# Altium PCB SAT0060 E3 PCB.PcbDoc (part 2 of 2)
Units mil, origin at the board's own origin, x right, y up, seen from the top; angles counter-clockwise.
Board outline 3780 x 2000 mil, 4 copper layers (Top Layer, L2_GND-Plane, L3_Sig-Layer, Bottom Layer), stack 61.2 mil thick; 136 components, 78 nets, 386 pads, 150 vias.
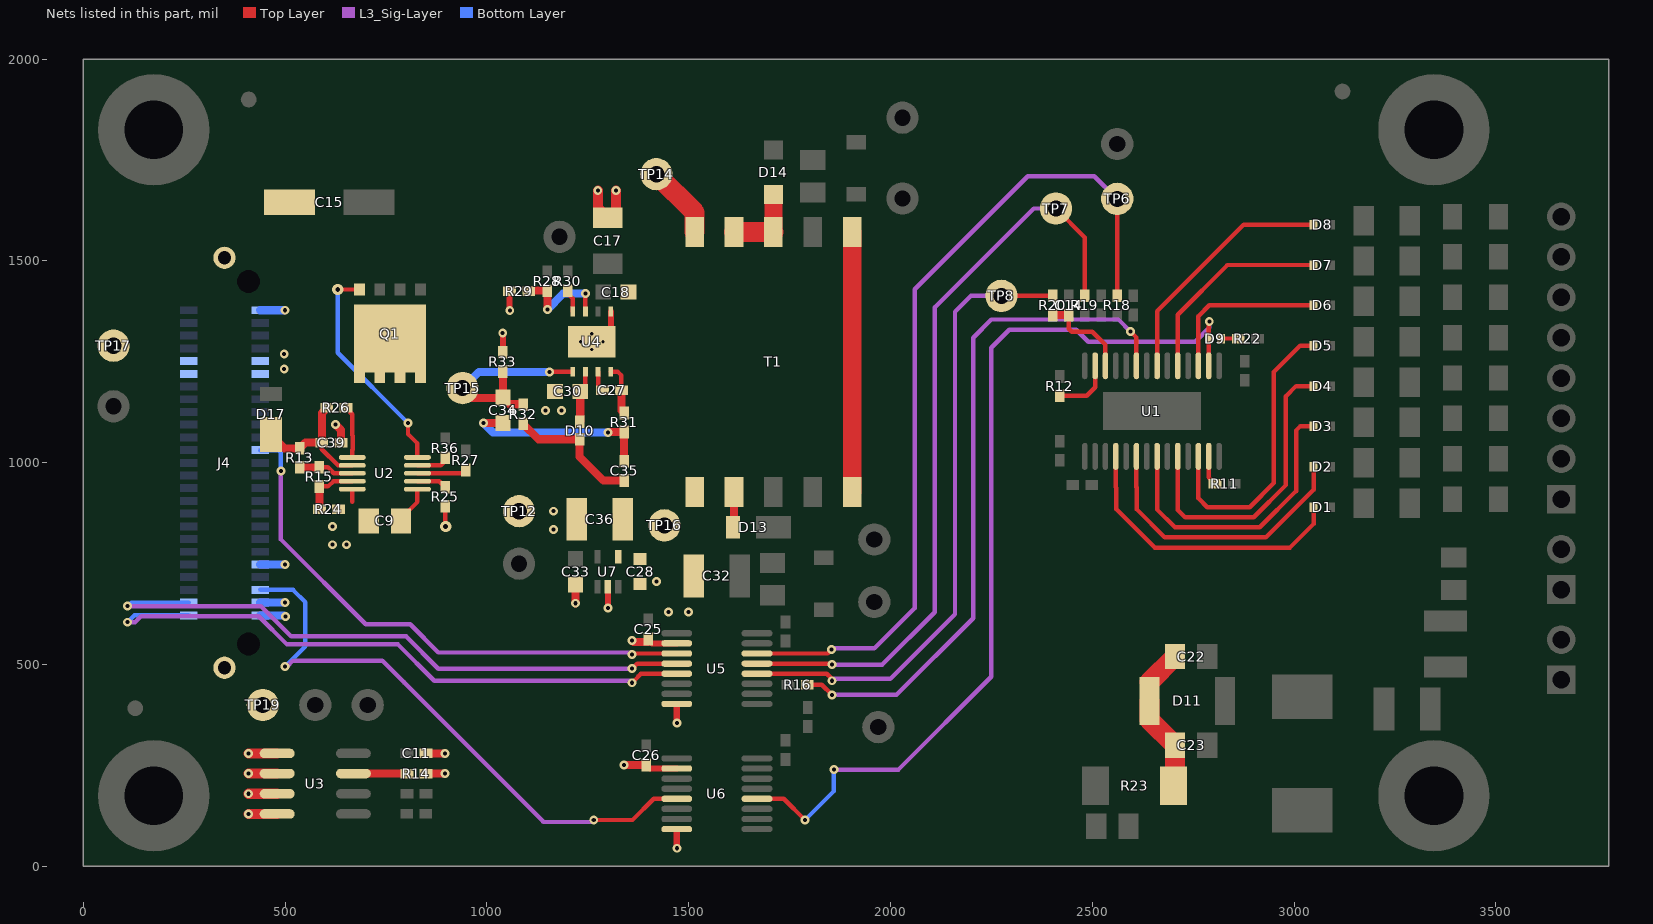
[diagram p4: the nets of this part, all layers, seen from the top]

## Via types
v1: diameter 22, hole 10, Top Layer to Bottom Layer, 126 vias
v2: diameter 15.75, hole 7.87, Top Layer to Bottom Layer, 18 vias
v3: diameter 19.68, hole 7.87, Top Layer to Bottom Layer, 4 vias
v4: diameter 28, hole 12, Top Layer to Bottom Layer, 2 vias

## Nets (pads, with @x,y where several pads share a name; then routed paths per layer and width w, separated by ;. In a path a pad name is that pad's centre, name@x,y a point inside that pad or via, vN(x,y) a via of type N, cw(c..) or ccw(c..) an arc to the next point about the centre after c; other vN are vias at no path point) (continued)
NCS0: J4.1 U5.5 | length 1615
  Top Layer w11: v1(1360,455) 1375.67,470.67 1375.67,471.3 1381.87,477.5 U5.5@1470.59,477.5 1468.79,475.7 U5.5@1477.97,475.7
  L3_Sig-Layer w11: v1(110,605) 128.41,605 143.41,620 435,620 505,550 780,550 870,460 1355,460 v1(1360,455)
  Bottom Layer w11: v1(110,605) 127.05,622.05 J4.1@261.42,622.05
NCS0_ISO: R20.2 TP8.1 U5.12 | length 1564.2
  Top Layer w11: U5.12@1669.41,477.5 1842.5,477.5 v1@1855,465 ; TP8.1@2275,1413.62 R20.2@2401.79,1413.62
  L3_Sig-Layer w11: v1@1860,465 2000,465 2160,625 2160,1374 2199.62,1413.62 TP8.1@2275,1413.62
  other v1: 1855,460
NetC9_1: C9.1 U2.6 | length 73.6
  Top Layer w11: C9.1@798.32,873.32 828.06,903.06 U2.6@828.06,934.64
NetC22_1: C22.1 C23.1 D11.2 R23.2 | length 322.6
  Top Layer w50: D11.2@2641.5,410 2641.5,363.5 C23.1@2705,300 R23.2@2705,203.54 ; D11.2@2641.5,456.5 C22.1@2705,520
NetC27_1: C27.1 U4.7 | length 49.6
  Top Layer w11: U4.7@1275.75,1225.2 1275.75,1190.63 C27.1@1286.38,1180
NetC27_2: C27.2 R31.1 T1.1 TP14.1 U4.8 | length 307.6
  Top Layer w11: U4.8@1307.24,1225.2 1324.8,1225.2 1333.62,1216.38 C27.2@1333.62,1180 ; R31.1@1333.62,1130 R31.1@1340,1123.62
  Top Layer w20: R31.1@1333.62,1130 C27.2@1333.62,1180
  Top Layer w50: TP14.1@1420,1715 1514.72,1620.28 T1.1@1514.72,1572.05
NetC30_1: C30.1 D10.1 U4.6 | length 109.3
  Top Layer w11: C30.1@1244.25,1192.76 U4.6@1244.25,1225.2
  Top Layer w20: D10.1@1231.5,1103.15 C30.1@1231.5,1180
NetC34_1: C34.1 C35.2 R31.2 | length 473.1
  Top Layer w20: v1(991.5,1098.5) C34.1@1040,1098.5 ; v1@1306.38,1076.38 R31.2@1340,1076.38 C35.2@1340,1003.62
  Bottom Layer w20: v1(991.5,1098.5) 1015,1075 v1(1300,1075)
NetC34_2: C34.2 R32.1 R33.2 TP15.1 U4.5 | length 506.4
  Top Layer w11: v1(1155.2,1225.2) U4.5@1212.76,1225.2
  Top Layer w20: TP15.1@940,1185 965,1160 1038.5,1160 C34.2@1040,1161.5 R33.2@1040,1226.38 ; C34.2@1051.5,1150 1056.5,1145 1088.62,1145 R32.1@1090,1143.62
  Bottom Layer w20: TP15.1@940,1185 980.2,1225.2 v1(1155.2,1225.2)
NetC39_1: C39.1 D17.1 R13.2 R26.1 U2.2 | length 345.4
  Top Layer w11: C39.1@591.38,1050 591.38,1033.62 631.3,993.7 U2.2@666.65,993.7
  Top Layer w20: D17.1@465,1069.8 498.96,1035.85 R13.2@537,1035.85 551.15,1050 C39.1@591.38,1050 591.38,1123.47 R26.1@603.73,1135.82
NetD9_1: D9.1 R22.1 | length 42.7
  Top Layer w11: D9.1@2819.43,1307.87 R22.1@2862.09,1307.87
NetD13_2: D13.2 T1.9 | length 89
  Top Layer w20: D13.2@1609.8,840 1612.36,842.56 T1.9@1612.36,927.95
NetD14_2: D14.2 T1.2 T1.3 | length 190.5
  Top Layer w45: T1.3@1710,1572.05 D14.2@1710,1664.88
  Top Layer w50: T1.2@1612.36,1572.05 T1.3@1710,1572.05
NetQ1_4: Q1.4 U2.10 | length 551.5
  Top Layer w11: v4(630.7,1429.3) Q1.4@684.51,1429.3 ; v1(804.76,1098.42) 804.76,1071.24 828.06,1047.94 U2.10@828.06,1013.38
  Bottom Layer w11: v4(630.7,1429.3) 630.7,1272.48 v1(804.76,1098.42)
NetQ1_5: Q1.5 Q1.6 Q1.7 Q1.8 Q1.9 R26.2 U2.1 | length 129.8
  Top Layer w11: R26.2@650.98,1135.82 666.65,1120.15 666.65,1068.34 667.67,1067.32 667.67,1032.68 666.65,1031.66 U2.1@666.65,1013.38
NetR11_2: R11.2 U1.13 | length 74.3
  Top Layer w11: U1.13@2788.68,1015.98 2788.68,963.82 R11.2@2804.31,948.19
NetR12_2: R12.2 U1.27 | length 149
  Top Layer w11: R12.2@2420,1166.38 2486.38,1166.38 2507.18,1187.18 U1.27@2507.18,1240.39
NetR13_1: R13.1 R15.2 U2.3 | length 135.7
  Top Layer w11: R15.2@580,988.62 R15.2@585,988.62 606.38,988.62 620.99,974.01 U2.3@666.65,974.01
  Top Layer w20: R13.1@537,988.6 R15.2@580,988.62
NetR14_1: R14.1 U3.7 | length 128.1
  Top Layer w11: U3.7@669.06,230 U3.7@669.49,230
  Top Layer w20: U3.7@669.49,230 R14.1@797.17,230
NetR15_1: R15.1 R24.2 U2.4 | length 143.5
  Top Layer w11: R15.1@585,941.38 606.38,941.38 619.33,954.33 U2.4@666.65,954.33
  Top Layer w20: R15.1@585,941.38 585,885.38 R24.2@585.38,885
NetR25_2: R25.2 U2.7 | length 75.5
  Top Layer w11: U2.7@828.06,954.33 882.47,954.33 R25.2@897.35,939.45
NetR27_2: R27.2 U2.8 | length 122.7
  Top Layer w11: U2.8@828.06,974.01 939.17,974.01 R27.2@947.35,982.2
NetR28_1: R28.1 R29.2 U4.3 | length 241.3
  Top Layer w11: U4.3@1244.25,1374.8 v1(1244.25,1419.25)
  Top Layer w20: R29.2@1110,1426.38 R28.1@1150,1426.38 v1(1150,1380)
  Bottom Layer w20: v1(1150,1380) 1189.25,1419.25 v1(1244.25,1419.25)
NetR30_1: R30.1 U4.4 | length 56.9
  Top Layer w11: R30.1@1200,1426.38 1200,1420 1212.76,1407.24 U4.4@1212.76,1374.8
NetR36_2: R36.2 U2.9 | length 80.9
  Top Layer w11: U2.9@828.06,993.7 885.7,993.7 897.2,1005.2 R36.2@897.2,1012.2
NetT1_5: T1.5 T1.6 | length 644.1
  Top Layer w45: T1.6@1905.28,927.95 T1.5@1905.28,1572.05
NHOT_ISO: D9.2 U1.16 U6.12 | length 2298.9
  Top Layer w11: U6.12@1669.41,167.5 1735.91,167.5 v1(1788.41,115) ; U1.16@2788.68,1240.39 D9.2@2788.68,1307.87 v1@2788.68,1343.68
  L3_Sig-Layer w11: v1(1860,240) 2020,240 2250,470 2250,1285 2294.3,1329.3 2460.7,1329.3 2490,1300 2755,1300 2790,1335 v1(2790,1350)
  Bottom Layer w11: v1(1788.41,115) 1860,186.59 v1(1860,240)
NLD: C14.1 R20.1 U1.26 | length 233.5
  Top Layer w11: C14.1@2441.79,1366.38 2441.79,1332.21 2449,1325 2500,1325 2532.77,1292.23 U1.26@2532.77,1240.39
  Top Layer w20: R20.1@2401.79,1366.38 C14.1@2441.79,1366.38
NSDRDY: J4.6 U6.5 | length 1466.5
  Top Layer w11: v1(1265,115) 1361,115 1413.5,167.5 U6.5@1470.59,167.5
  L3_Sig-Layer w11: v1@505,495 520,510 741,510 795.2,455.8 ; 795.2,454.8 795.2,455.8 ; 1140,110 1260,110 v1(1265,115) ; 1140,111 795.2,455.8
  Bottom Layer w11: J4.6@438.58,685.04 519.96,685.04 550,655 550,545 v1(500,495)
PLC_GND: C9.2 C11.2 C15.2 C17.2 C18.2 C25.2 C26.2 C28.1 C30.2 C32.2 C33.2 C36.2 C39.2 J4.2 J4.4 J4.10 J4.39 J4.40 J4.41 J4.42 J4.50 J4.MH1 J4.MH2 R14.2 R24.1 R25.1 R29.1 R33.1 TP12.1 TP17.1 TP19.1 U2.5 U3.1 U3.2 U3.3 U3.4 U4.1 U4.9 U5.2 U5.8 U6.2 U6.8 U7.2 | length 1552.2
  Top Layer w11: 666.65,903.65 U2.5@666.65,934.64 ; R25.1@897.35,892.2 897.35,842.65 v4(898,842)
  Top Layer w15: R33.1@1040,1273.62 v1@1040,1320.53 ; v1@1056.38,1378.09 R29.1@1056.38,1425 ; U4.9@1260,1300 1283,1300 1307.24,1324.24 U4.1@1307.24,1374.8 ; v1(1300,640) U7.2@1300,692.91 ; C26.2@1395,251.38 1403.88,242.5 U6.2@1470.59,242.5 ; C25.2@1400,561.38 1408.88,552.5 U5.2@1470.59,552.5 ; v1@1470.59,45.59 U6.8@1470.59,92.5 ; v1@1470.59,355.59 U5.8@1470.59,402.5
  Top Layer w20: v1(625,1095) 638.62,1081.38 C39.2@638.62,1050 ; R14.2@849.41,230 v1(896.22,230) ; C11.2@849.41,280 v1(896.22,280) ; v1(1220,652.01) C33.2@1220,698.82 ; C36.2@1222.91,852.09 C36.2@1222.91,860 ; v1(1340,251.38) C26.2@1395,251.38 ; v1(1360,560) 1363.62,556.38 C25.2@1400,556.38
  Top Layer w25: v1(410,130) U3.4@480.51,130 ; v1(410,180) U3.3@480.51,180 ; v1(410,230) U3.2@480.51,230 ; v1(410,280) U3.1@480.51,280 ; v1(1275,1675) 1275,1632.09 C17.2@1300,1607.09 1320,1627.09 v1(1320,1675)
  Bottom Layer w20: J4.2@438.58,622.05 v1@492.95,622.05 ; J4.4@438.58,653.54 v1@497.95,653.54 ; J4.10@438.58,748.03 v1@497.95,748.03 ; J4.50@438.58,1377.95 v1@497.95,1377.95 ; v1@497.95,622.05 v1(501,619)
  other v1: 1471.18,45 1471.18,355 1450,630 1500,630 500,653.54 1420,706 500,748.03 618,797 652,797 1165,835 618,842 1165,880 1145,1130 1185,1130 498,1232 498,1270 1039.41,1321.12 500,1377.95 1056.97,1377.5
  other v3: 1260,1280.32 1232.44,1300 1287.56,1300 1260,1319.68
RE0: D1.1 U1.4 | length 727.5
  Top Layer w11: U1.4@2558.37,1015.98 2558.37,940 2560,938.37 2560,885 2655,790 2990,790 3048.35,848.35 D1.1@3048.35,888.35 ; D1.1@3048.35,890 D1.1@3048.35,888.35 ; D1.1@3050,890 D1.1@3048.35,888.35
RE1: D2.1 U1.6 | length 704.2
  Top Layer w11: U1.6@2609.55,1015.98 2609.55,940 2610.7,938.85 2610.7,884.3 2680,815 2930,815 3048.35,933.35 D2.1@3048.35,990
RE2: D3.1 U1.8 | length 729.1
  Top Layer w11: U1.8@2660.73,1015.98 2660.73,884.27 2705,840 2915,840 3005,930 3005,1080 3015,1090 D3.1@3048.35,1090
RE3: D4.1 U1.10 | length 740.3
  Top Layer w11: U1.10@2711.91,1015.98 2711.91,883.09 2730,865 2900,865 2980,945 2980,1165 3005,1190 D4.1@3048.35,1190
RE4: D5.1 U1.12 | length 725.2
  Top Layer w11: U1.12@2763.09,1015.98 2763.09,911.91 2785,890 2890,890 2950,950 2950,1225 3015,1290 D5.1@3048.35,1290
RE5: D6.1 U1.17 | length 419.1
  Top Layer w11: U1.17@2763.09,1240.39 2763.09,1363.09 2790,1390 D6.1@3048.35,1390
RE6: D7.1 U1.19 | length 513.9
  Top Layer w11: U1.19@2711.91,1240.39 2711.91,1366.91 2835,1490 D7.1@3048.35,1490
RE7: D8.1 U1.21 | length 613.5
  Top Layer w11: U1.21@2660.73,1240.39 2660.73,1375.73 2875,1590 D8.1@3050.13,1590
S1GPO0: J4.28 U5.3 | length 1368.8
  Top Layer w11: v1(1360,525) 1362.5,527.5 U5.3@1470.59,527.5
  L3_Sig-Layer w11: v1(490,980) 490,810 700,600 810,600 880,530 1355,530 v1(1360,525)
  Bottom Layer w11: J4.28@438.58,1031.5 483.5,1031.5 490,1025 v1(490,980)
S1GPO0_ISO: R18.2 TP6.1 U5.14 | length 2127.2
  Top Layer w11: U5.14@1669.41,527.5 1844.5,527.5 v1(1854,537) ; R18.2@2561.79,1413.62 TP6.1@2561.79,1654.12
  L3_Sig-Layer w11: v1@1857,540 1960,540 2060,640 2060,1430 2340,1710 2505,1710 2560,1655 TP6.1@2560,1630
SCLK: J4.3 U5.4 | length 1572.8
  Top Layer w11: v1(1360,490) 1372.5,502.5 U5.4@1470.59,502.5
  L3_Sig-Layer w11: v1(110,645) 440,645 515,570 800,570 880,490 v1(1360,490)
  Bottom Layer w11: 118.54,653.54 J4.3@261.42,653.54
SCLK_ISO: R19.2 TP7.1 U5.13 | length 1894.5
  Top Layer w11: U5.13@1669.41,502.5 v1@1852.5,502.5 ; TP7.1@2410,1630 2481.79,1558.21 R19.2@2481.79,1413.62
  L3_Sig-Layer w11: v1(1855,500) 1980,500 2110,630 2110,1385 2355,1630 TP7.1@2410,1630
SOP: R16.1 U1.23 | length 1707.1
  Top Layer w11: R16.1@1793.62,450 1830,450 v1(1855,425) ; v1(2595,1325) 2609.55,1310.45 U1.23@2609.55,1240.39
  L3_Sig-Layer w11: v1(1855,425) 2015,425 2205,615 2205,1310 2250,1355 2565,1355 v1(2595,1325)
VPRI: C28.2 C35.1 C36.1 D10.2 R32.2 T1.10 TP16.1 U7.4 | length 333.4
  Top Layer w20: R32.2@1090,1096.38 1128.03,1058.35 D10.2@1230,1058.35 1230,1015 1288.62,956.38 C35.1@1340,956.38
pads on no net: FID1.1 FID2.1 FID3.1 H1.1 H2.1 H5.1 H6.1 J4.7 J4.8 J4.9 J4.13 J4.14 J4.15 J4.16 J4.17 J4.18 J4.19 J4.20 J4.21 J4.22 J4.23 J4.24 J4.25 J4.26 J4.30 J4.31 J4.32 J4.33 J4.34 J4.43 J4.44 J4.45 J4.46 J4.47 J4.48 J4.49 J4.MH3 J4.MH4 LBL1.0 T1.7 T1.8 U1.14 U6.6 U6.11 U7.1 U7.3

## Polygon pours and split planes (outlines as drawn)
PLC_GND on Bottom Layer "Bottom Layer-No Net" (solid, remove dead copper, shelved, pour order 7): 15.9,1980 1540,1980 1540,20 6.32,20 6.32,1960.4 15.9,1970.2
ISO_GND on Bottom Layer "Top Layer-No Net" (solid, shelved, pour order 8): 1604.77,1975.07 1599.85,1970.05 1599.85,20 3760.98,20 3765.81,24.93 3765.81,1980 1604.67,1980 1590,1965.02 1594.92,1970.05 1599.85,1970.05 1599.85,1975.07
PLC_GND on Top Layer "Top Layer-No Net 1" (solid, shelved, pour order 6): 6.32,2000.53 6.32,29.89 0.19,15 2.23,19.96 1540,19.96 1540,1980.53 1535.05,1980.53 1529.79,1980.68 8.44,1980.68
ISO_GND on Top Layer "Top Layer-No Net" (solid, remove dead copper, shelved, pour order 5): 1604.94,1971.13 1600.02,1966.11 1600.02,16.06 3761.16,16.06 3765.98,20.99 3765.98,1976.06 1604.85,1976.06 1590.17,1961.08 1595.1,1966.11 1600.02,1966.11 1600.02,1971.13
ISO_GND on Top Layer "Top Layer-No Net" (hatched 90Degree grid 5 track 8, remove dead copper, pour order 36): 1660,98.01 1660,49.43 1670,39.72 1680,30 1735,30 3205,30 3225,49.43 3225,185.46 3225,300.11 3208,316.63 3198,326.35 3170,326.35 3143,300.11 3070,229.18 2948,229.18 2825,229.18 2800,204.89 2740,146.6 2623,146.6 2579,146.6 2560,128.13 2560,78.58 2550,68.87 2460,68.87 2430,68.87 2420,78.58 2420,151.45 2420,370.07 2310,476.95 2065,715 1910,715 1885,690.71 1725,690.71 1675,690.71 1660,676.13 1660,627.55 1660,98.01
PLC_GND on Top Layer "Top Layer-No Net" (hatched 90Degree grid 5 track 8, remove dead copper, pour order 26): 1400,1460 1410,1450 1410,1345 1325,1260 1125,1260 1115,1270 1115,1310 1140,1335 1339.65,1335 1354,1349.35 1354,1450.27 1363.73,1460
ISO_GND on Top Layer "Top Layer-No Net" (hatched 90Degree grid 5 track 8, remove dead copper, pour order 35): 3350,825 3695,825 3715,806.41 3715,778.53 3700,764.59 3690,755.29 3610,755.29 3455,755.29 3450,750.65 3445,746 3365,746 3340,746 3325,759.94 3320,764.59 3320,801.76 3320,811.06 3335,825 3350,825
PLC_GND on Top Layer "Top Layer-No Net" (hatched 90Degree grid 5 track 8, remove dead copper, pour order 34): 1450,715 1475,740 1515,740 1525,730 1525,625 1510,610 1450,610 1435,625 1435,650 1415,670 1365,670 1355,680 1355,710 1360,715
PLC_GND on Top Layer "Top Layer-No Net" (hatched 90Degree grid 5 track 8, remove dead copper, pour order 33): 1245,805 1155,805 1135,825 1130,830 1075,830 1030,830 1020,840 1015,845 1015,905 1015,935 1030,950 1090,950 1225,950 1235,940 1245,930 1245,910 1245,805
ISO_GND on Top Layer "Top Layer-No Net" (hatched 90Degree grid 5 track 8, remove dead copper, pour order 32): 3240,439 3240,300 3175,235 3175,70 3160,55 2815,55 2800,70 2800,190 2825,215 3070,215 3175,320 3175,435 3179,439
24V_LIMIT on Top Layer "Top Layer-No Net" (hatched 90Degree grid 5 track 8, remove dead copper, pour order 30): 945,1020 915,1050 860,1050 850,1060 850,1090 860,1100 920,1100 965,1055 1015,1055 1025,1045 1025,1030 1015,1020
PLC_GND on Top Layer "Top Layer-No Net" (hatched 90Degree grid 5 track 8, remove dead copper, pour order 29): 715,780 725,790 725,875 720,880 690,880 685,885 685,905 680,910 625,910 620,905 620,865 600,845 600,790 610,780
24V_LIMIT on Top Layer "Top Layer-No Net" (hatched 90Degree grid 5 track 8, remove dead copper, pour order 28): 1305,1410 1285,1410 1270,1420 1270,1455 1260,1465 965,1465 925,1425 828,1425 724,1426 710,1440 710,1510 640,1580 640,1840 665,1865 900,1865 950,1815 1090,1815 1235,1670 1235,1555 1250,1540 1300,1540 1310,1530 1310,1415
PLC_GND on Top Layer "Top Layer-No Net" (hatched 90Degree grid 5 track 8, remove dead copper, pour order 25): 1185,1115 1140,1115 1130,1125 1130,1185 1140.02,1195 1178.35,1195 1190,1190 1190,1120
PLC_GND on Top Layer "Top Layer-No Net" (hatched 90Degree grid 5 track 8, remove dead copper, pour order 24): 425,1360 535,1360 555,1360 580,1385 580,1455 580,1775 560,1795 555,1800 460,1800 410,1800 400,1790 300,1690 300,1550 300,1390 330,1360 425,1360
NetQ1_5 on Top Layer "Top Layer-No Net" (hatched 90Degree grid 5 track 8, remove dead copper, pour order 23): 684,1110 655.15,1110 641.13,1124.01 641.13,1178.87 640,1180 640,1385 649.96,1395 860,1395 870,1385 870,1310 870.04,1285 870.04,1145.04 850,1125 699,1125
ISO_GND on Top Layer "Top Layer-No Net" (hatched 90Degree grid 5 track 8, remove dead copper, pour order 27): 2675,130 2680,125 2680,70 2670,60 2575,60 2560,75 2560,130 2565,135 2585,135 2590,130
PLC_GND on Top Layer "Top Layer-No Net" (hatched 90Degree grid 5 track 8, remove dead copper, pour order 40): 1485,40 1485,585 1521,621 1521,727 1508,740 1295,740 1265,770 1265,940 1415,1090 1415,1585 1445,1615 1500,1615 1525,1640 1525,1965 1515,1975 155,1975 40,1860 40,130 135,35 1480,35
ISO_GND on Top Layer "Top Layer-No Net" (hatched 90Degree grid 5 track 8, remove dead copper, pour order 38): 2000,880 2030,850 2090,850 2550,390 2550,265 2560,255 2640,255 2650,265 2650,300 2605,345 2605,525 2670,590 2730,590 2890,750 3730,750 3750,770 3750,1955 3730,1975 1635,1975 1615,1955 1615,1645 1630,1635 1950,1635 2000,1585
24V_LIMIT on Bottom Layer "Top Layer-No Net" (hatched 90Degree grid 5 track 8, remove dead copper, pour order 31): 1015,1010 850,1010 835,1025 835,1100 835,1108 783,1160 748,1195 748,1775 778,1805 923,1805 933,1795 968,1760 968,1735 968,1484 935,1451 885,1401 885,1280 885,1140 905,1120 974,1051 980,1051 1015,1051 1025,1041 1025,1020 1025,1015 1020,1010 1015,1010
PLC_GND on Bottom Layer "Top Layer-No Net" (hatched 90Degree grid 5 track 8, remove dead copper, pour order 39): 1485,40 1485,585 1521,621 1521,727 1508,740 1295,740 1265,770 1265,940 1415,1090 1415,1585 1445,1615 1505,1615 1520,1630 1520,1950 1495,1975 155,1975 40,1860 40,130 135,35 1480,35
ISO_GND on Bottom Layer "Top Layer-No Net" (hatched 90Degree grid 5 track 8, remove dead copper, pour order 37): 2000,915 1885,850 1885,700 1661.2,700 1660,381 1660,51 1683,30 2508,50 3700,50 3750,100 3750,1955 3730,1975 1640,1975 1615,1950 1615,1650 1630,1635 1950,1635 2000,1585
ISO_GND on L2_GND-Plane (split plane): 3759.9,20.1 1605.09,20.1 1605.09,1979.9 3759.9,1979.9
PLC_GND on L2_GND-Plane (split plane): 1534.9,20.1 20.1,20.1 20.1,1979.9 1534.9,1979.9

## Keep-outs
Keep-Out Layer:
  text ".Layer_Name" at 577,-858.49 h60

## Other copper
Top Layer:
  rectangle net PLC_GND: 1497,545 1524,560
  pour cut-out: 615,1040 650,1040 655,1035 655,1015 650,1010 625,1010 610,1025 610,1035
  pour cut-out: 705,935 710,930 710,920 700,910 615,910 615,930 620,935
  pour cut-out: 613.58,900 645,931.42 645,960 640,965 610,965 606.38,961.38 606.38,923.38 600,917 600,900
  pour cut-out: 3249,443.15 3135.29,443.15 3135.29,475.29 3230,570 3270,570 3270,309 3249,289
  region net 24V_FIELD: 3712.43,723 3712.43,643.25 3557.44,643.25 3494.19,580 3221,580 3120,479 3120,350 2913.59,350 2823.59,260 2754,260 2754,331.44 2790.12,367.56 2790.12,452.88 2757,486 2757,567 2895,705 3502.21,705 3520.21,723
  region net EARTH_GND: 3710.01,610 3710.01,380.01 3666.85,336.85 3309,336.85 3309,530 3540,530 3627.99,610
  region net 5V_ISO: 2469.77,957.46 2469.77,870 2382.23,870 2294.77,957.46 2294.77,1297 2368,1297 2438,1227 2438,1194 2374,1194 2344.77,1164.77 2344.77,1073 2436,1073 2436,1036 2344.77,1036 2344.77,985.23 2372.54,957.46
  pour cut-out: 3431.54,1656.5 3468.46,1656.5 3468.46,863.5 3431.54,863.5
  pour cut-out: 920.67,906.7 920.5,906.53 920.5,768 596.5,768 596.5,861.35 581.5,861.35 581.5,759 587.5,753 936.5,753 936.5,902 928.5,910 925.2,906.7
  pour cut-out: -15,1865 -15,1985 105,1985 115,1975 5,1865
  pour cut-out: 110,10 -10,10 -10,130 0,140 110,30
  region net 24V_PLC: 435.82,1199 435.82,1145 565,1145 579.85,1159.85 579.85,1231 535,1231 535,1199
  region net NetC27_2: 1539.97,1600 1510.12,1600.12 1490,1580 1490,1410 1320,1240 1300,1240 1300,1213 1318,1195 1318,1106 1357,1106 1357,1202 1540,1385 1540,1570
  region net VPRI: 1540,860 1425,745 1310,745 1310,956.81 1323.19,970 1540,970
  region net ISO_GND: 3100.5,75 2829.5,75 2805.5,99 2805.5,179 2830.5,204 3100.5,204
  pour cut-out: 2893,1371 2892.84,1370.84 2892.84,1333.7 2810.79,1333.7 2809,1331.91 2809,1376 2893,1376
  region net NetC39_1: 620,1124 603,1107 603,1020 431,1020 431,1118.4 442.3,1129.71 569.71,1129.71 592,1152 620,1152
  pour cut-out: 746.35,901.32 700.32,901.32 699,900 699,1034 683,1034 684,1110 763.81,1107.89 762.66,1072.42 783.32,1071.38 806.22,1032.62 786,1008 780.94,943.49 805,900
  text ".Layer_Name" at 577,-858.49 h60
L3_Sig-Layer:
  text ".Layer_Name" at 565,-860 h60
Bottom Layer:
  rectangle net PLC_GND: 597,824 643,1115
  region net 5V_ISO: 2108,1478.22 2165,1478.22 2165,544 2108,544
  pour cut-out: 581.21,1131.29 581.21,1116 657.65,1116 657.65,1131.29
  pour cut-out: 581.35,824 596.65,824 596.65,1115 581.35,1115
  pour cut-out: 642.35,824 657.65,824 657.65,1115.32 642.35,1115.32
  pour cut-out: 581.21,823.29 581.21,808 657.65,808 657.65,823.29
  region net PLC_GND: 20,1211.1 20,1350 135,1350 178.48,1263.03 478,1265 478,1293 520,1293 520,1211.1
  region net 24V_PLC: 20,1199 20,1090 140,1090 168.52,1147.04 580,1145 580,1232 535,1232 535,1199
  text ".Layer_Name" at 577,-858.49 h60
L2_GND-Plane (plane layer: these items are gaps in the copper):
  rectangle: 595.35,822 641,862.32
  rectangle: 602.35,1075 648,1115.32
  lines w10: 1540,-10 1540,2010
  lines w60: 1575,20 1575,1980
  text ".Layer_Name" at 575,-860 h60

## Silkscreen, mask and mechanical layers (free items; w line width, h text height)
Top Overlay:
  lines w8: 957,1243 1003,1289 1003,1319 ; 1878,735 2075,735 ; 2116.16,682.45 2084,682.45 2074,692.45 2074,779.55 2074,785.29 2081.16,792.45 2116.16,792.45 ; 3139,1821 3139,1683 ; 3173,697 3173,835 ; 3139,1683 3129,1693 3149,1693 3139,1683 ; 3173,835 3163,825 3183,825 3173,835
  text "GND" at 3510,735 h40 r90
  text "SAT0060 E2" at 301.57,660.82 h40 r90
  text "ISE-PLC-DIM-100" at 373,660 h40 r90
  text "24V" at 3515,645 h40 r90
  text "EARTH_GND" at 3510,380 h40 r90
  text ".Layer_Name" at 577,-858.49 h50
Bottom Overlay:
  text "50" at 561,1402 h45
  text "49" at 217,1370 h45
  text "1" at 212,591 h45
  text "2" at 518,553 h45
  text ".Layer_Name" at 577,-858.49 h60
Top Paste:
  text ".Layer_Name" at 577,-858.49 h60
Bottom Paste:
  text ".Layer_Name" at 577,-858.49 h60
Top Solder:
  text ".Layer_Name" at 577,-858.49 h60
  text ".Layer_Name" at 577,-858.49 h60
Bottom Solder:
  text ".Layer_Name" at 577,-858.49 h60
Drill Guide:
  text ".Layer_Name" at 577,-858.49 h60
M1 Board Outline:
  the board outline again, w10
  text ".Layer_Name" at 577,-858.49 h60
M2 Board Dimensions:
  rectangle: -0.5,-285.5 124.5,-160.5
  rectangle: 124.5,-410.5 499.5,-285.5
  lines w7: -0.5,-285.5 999.5,-285.5 ; 124.5,-410.5 124.5,-160.5 ; 249.5,-410.5 249.5,-160.5 ; 499.5,-410.5 499.5,-160.5 ; 749.5,-410.5 749.5,-160.5 ; -0.5,-410.5 999.5,-410.5 999.5,-160.5 -0.5,-160.5 -0.5,-410.5
  lines w10: -0.5,-475.5 -0.5,-455.5 ; 59.5,-485.5 -0.5,-465.5 ; 59.5,-445.5 -0.5,-465.5 ; 223.58,-465.5 -0.5,-465.5 ; 775.42,-465.5 999.5,-465.5 ; 939.5,-485.5 999.5,-465.5 ; 939.5,-445.5 999.5,-465.5 ; 999.5,-475.5 999.5,-455.5
  text "1000 (mil)" at 233.58,-501.49 h60
  text ".Layer_Name" at 577,-858.49 h60
M3 3D STEP Top:
  text ".Layer_Name" at 577,-858.49 h60
M4 3D STEP Bottom:
  text ".Layer_Name" at 577,-858.49 h60
M5 Assembly Top:
  lines w10: -292,-930.17 6308,-930.17 ; -292,-726.83 6310,-726.83 ; -292,-523.5 -292,-1133.5 3713,-1133.5 6310,-1133.5 6310,-523.5 -291.5,-523.5 -291.5,-1133.5 1284,-1133.5 ; 2173,-1133.5 2173,-523.5 ; 3440,-726.83 3440,-523.5 ; 4280,-726.83 4280,-523.5 ; 4902,-1140 4902,-937.17
  text "COMPONENTS MARKED 'DNP' SHOULD NOT BE POPULATED." at 1153.5,-318.5 h60
  text "ASSEMBLY VARIANT:" at 1153,-434 h60
  text ".VariantName" at 2189,-434 h60
  text "PCB VIEWED FROM TOP SIDE" at -228.5,-655.67 h60
  text "BOARD #:" at 2248,-655.67 h60
  text ".PRJ_Number" at 2793.5,-655.67 h60
  text "REV:" at 3638,-655.67 h60
  text ".PCB_Rev" at 3929.5,-655.67 h60
  text "SVN REV:" at 4476,-655.67 h60
  text ".VersionControl_RevNumber" at 4982,-655.67 h60
  text "IGNORE ->" at -228.5,-858.49 h60
  text "PLOT NAME =" at -228.5,-1064.34 h60
  text ".plot_File_Name" at 577,-1064.34 h60
  text "GENERATED    :" at 2250,-1064.34 h60
  text ".Print_Date" at 3119.5,-1064.34 h60
  text ".Print_Time" at 3848.5,-1064.34 h60
  text "TEXAS INSTRUMENTS" at 5113,-1064.34 h60
M6 Assembly Bottom:
  lines w10: -292.5,-727.33 6309.5,-727.33 ; -290.5,-930.67 6309.5,-930.67 ; 1115.5,-1140.5 1115.5,-937.67 ; 1737.5,-727.33 1737.5,-524 ; 2577.5,-727.33 2577.5,-524 ; 3844.5,-1134 3844.5,-524 ; 4733.5,-1134 6309,-1134 6309,-524 -292.5,-524 -292.5,-1134 2304.5,-1134 6309.5,-1134 6309.5,-524
  text "COMPONENTS MARKED 'DNP' SHOULD NOT BE POPULATED." at 6102,-318 h60
  text ".VariantName" at 5058,-434 h60
  text "ASSEMBLY VARIANT:" at 6097,-434 h60
  text ".VersionControl_RevNumber" at 1035.5,-656.17 h60
  text "SVN REV:" at 1541.5,-656.17 h60
  text ".PCB_Rev" at 2088,-656.17 h60
  text "REV:" at 2379.5,-656.17 h60
  text ".PRJ_Number" at 3224,-656.17 h60
  text "BOARD #:" at 3769.5,-656.17 h60
  text "PCB VIEWED FROM BOTTOM SIDE" at 6246,-656.17 h60
  text "IGNORE ->" at 2547.85,-858.49 h60
  text "TEXAS INSTRUMENTS" at 904.5,-1064.84 h60
  text ".Print_Time" at 2169,-1064.84 h60
  text ".Print_Date" at 2898,-1064.84 h60
  text "GENERATED    :" at 3767.5,-1064.84 h60
  text ".plot_File_Name" at 5440.5,-1064.84 h60
  text "PLOT NAME =" at 6246,-1064.84 h60
M9 Title Sheet:
  drawing of 57 lines, arcs and shapes, not listed
  text "1" at 739.84,8036.5 h70
  text "2" at 3235.5,8036.5 h70
  text "3" at 5724.84,8036.5 h70
  text "4" at 8231.51,8036.5 h70
  text "5" at 10730.5,8036.5 h70
  text "6" at 13235.5,8036.5 h70
  text "A" at -416.5,6893.5 h70
  text "A" at 14383.5,6893.5 h70
  text "B" at -416.5,4513.5 h70
  text "B" at 14383.5,4513.5 h70
  text "C" at -416.5,2138.5 h70
  text "C" at 14383.5,2138.5 h70
  text "PROJECT TITLE:" at 11343.5,277.5 h45
  text ".PRJ_Title" at 11393.5,144.17 h70
  text "DESIGNED FOR:" at 11343.5,-23.5 h45
  text ".PRJ_Customer" at 11393.5,-163.5 h70
  text "D" at -416.5,-231.5 h70
  text "D" at 14383.5,-231.5 h70
  text "FILE NAME:" at 11343.5,-323.5 h45
  text ".PCB_File_Name_No_Path" at 11393.5,-443.5 h70
  text "Texas Instruments (TI) and/or its licensors do not warrant the accuracy or completeness of this specification" at 6374,-605.34 h45
  text "ENGINEER:" at 11343.5,-613.5 h45
  text "LAYOUT BY:" at 12848.5,-613.5 h45
  text "or any information contained therein. TI and/or its licensors do not warrant that this design will meet" at 6329.01,-718 h45
  text ".PRJ_Engineer" at 11393.5,-768.49 h70
  text ".PCB_Layout" at 12899,-768.49 h70
  text "the specifications, will be suitable for your application or fit for any particular purpose, or will operate in" at 6329.01,-830.67 h45
  text ".Layer_Name" at 577,-858.49 h60
  text "ALTIUM DESIGNER VERSION:" at 12848.5,-923.5 h45
  text "an implementation. TI and/or its licensors do not warrant that the design is production worthy. You should" at 6329.01,-943.33 h45
  text "completely validate and test your design implementation to confirm the system functionality for your application." at 6374,-1056 h45
  text ".print_Scale" at 11393.5,-1056.83 h70
  text ".Application_BuildNumber" at 12899,-1056.83 h70
  text "1" at 739.84,-1263.5 h70
  text "2" at 3235.5,-1263.5 h70
  text "3" at 5724.84,-1263.5 h70
  text "4" at 8231.51,-1263.5 h70
  text "5" at 10730.5,-1263.5 h70
  text "6" at 13235.5,-1263.5 h70
M10 Fab Notes:
  drawing of 212 lines, arcs and shapes, not listed
  text "DESIGN INFORMATION" at 12381.02,6810 h60
  text "(REFER ALSO ARRAY/PANEL PROFILING INFORMATION)" at 12019.46,6648.29 h60
  text "BOARD SIZE" at 11333.46,6644 h60
  text "3780MIL" at 11795.78,6516.18 h60
  text "X" at 12301.46,6516.18 h60
  text "2000MIL" at 12532.78,6516.18 h60
  text "Number of Layers :" at 11736.46,6319 h60
  text "4" at 12831.27,6309 h60
  text "MIN. TRACK WIDTH:" at 11736.46,6180 h60
  text "11" at 12832.7,6180 h60
  text "MIL" at 12987.46,6180 h60
  text "MIN. CLEARANCE:" at 11736.46,6048 h60
  text "8" at 12832.7,6048 h60
  text "MIL" at 12987.46,6048 h60
  text "MIN. VIA PAD SIZE:" at 11736.46,5916 h60
  text "22" at 12802.71,5916 h60
  text "MIL" at 12987.46,5916 h60
  text "0.05mm (2MIL)" at 12431.46,5774.29 h60
  text "MINIMUM ANNULAR RING" at 11407.23,5770 h60
  text "EXTERNAL" at 13139.46,5770 h60
  text "PER" at 11607.23,5652 h60
  text "IPC-D-275 CLASS 2 LEVEL C" at 11827.23,5652 h60
  text "MIL, HOLES" at 13315.46,5539.71 h60
  text "+/-" at 12923,5539 h60
  text "+/-" at 13777,5539 h60
  text "REGISTRATION TOLERANCES:" at 11407.23,5534 h60
  text "METAL" at 12607,5534 h60
  text "5" at 13183.2,5534 h60
  text "3" at 14016.2,5534 h60
  text "MIL" at 14132.46,5534 h60
  text "MATERIAL:" at 11332.46,5324.54 h60
  text "FR-4 High Tg" at 12318.9,5184.21 h60
  text "FR-408" at 11753.46,5175.64 h60
  text "X" at 12165.46,5175.64 h60
  text "OTHER" at 13241.46,5175.64 h60
  text "62 MIL (1.6mm) +/-10%" at 12073.56,5012.92 h60
  text "THICKNESS:" at 11407.23,5008.64 h60
  text "X" at 11945.4,5008.64 h60
  text "OTHER" at 13358.46,5008.64 h60
  text "TOLERANCE:" at 11407.23,4850.64 h60
  text "X" at 12246.53,4850.64 h60
  text "ANSI IPC-6012 TYPE 3 CLASS 2" at 12433.48,4850.64 h60
  text "OTHER +/-" at 12433.46,4694.64 h60
  text "BOW & TWIST:" at 11407.23,4537.64 h60
  text "X" at 12246.53,4537.64 h60
  text "ANSI IPC-6012 TYPE 3 CLASS 2" at 12433.48,4537.64 h60
  text "OTHER +/-" at 12433.46,4379.13 h60
  text "COPPER THICKNESS (FINISHED):" at 11332.46,4243.64 h60
  text "1.4MIL (1oz)" at 12212.46,4090.92 h60
  text "2MIL (1.4oz)" at 12979.46,4090.92 h60
  text "2.8MIL (2oz)" at 13706.46,4090.92 h60
  text "OUTER:" at 11689.46,4086.64 h60
  text "X" at 12084,4086 h60
  text "1.4MIL (1oz)" at 12212.46,3933.92 h60
  text "2.8MIL (2oz)" at 12979.46,3933.92 h60
  text "N/A" at 13706,3934.29 h60
  text "INNER SIGNAL:" at 11400.38,3929.64 h60
  text "X" at 12085.42,3929.64 h60
  text "DRILLING:" at 11332.46,3790.64 h60
  text "REFERENCE:" at 11407.23,3673.64 h60
  text "X" at 12055.46,3673.64 h60
  text "AS SHOWN" at 12242.46,3673.64 h60
  text "X" at 12956.46,3673.64 h60
  text "NC_DRILL FILES" at 13093.46,3673.64 h60
  text "PTH MIN COPPER THICKNESS:" at 11407.23,3515.64 h60
  text "X" at 12757.46,3515.64 h60
  text "1MIL" at 12894.46,3515.64 h60
  text "OTHER" at 13391.46,3515.64 h60
  text "BOARD FINISH:" at 11332.46,3356.64 h60
  text "SILKSCREEN:" at 11487.68,3238.64 h60
  text "X" at 12436.46,3238.64 h60
  text "TOP" at 12562.46,3238.64 h60
  text "BOTTOM" at 13073.46,3238.64 h60
  text "SILKSCREEN COLOR:" at 11487.68,3071.64 h60
  text "X" at 12435.42,3071.64 h60
  text "WHITE" at 12562.46,3071.64 h60
  text "OTHER" at 13073.46,3071.64 h60
  text "SOLDER RESIST COLOR:" at 11487.68,2901.64 h60
  text "X" at 12055.42,2742.44 h60
  text "GREEN" at 12182.46,2742.44 h60
  text "BLUE" at 12773.46,2742.44 h60
  text "OTHER" at 13311.46,2742.44 h60
  text "IMMERSION GOLD (ENIG)" at 12393.46,2553.92 h60
  text "ENEPIG" at 13731,2550.64 h60
  text "SURFACE FINISH:" at 11332.46,2549.64 h60
  text "X" at 12206.51,2549.64 h60
  text "IMM. TIN/SILVER OR EQUIV" at 11662,2392.64 h60
  text "OTHER" at 13093.46,2392.64 h60
  text "ARRAY/PANEL:" at 11332.46,2213.64 h60
  text "CUT AND TRIM PER MECH LAYER 1" at 12393.46,2209.35 h60
  text "N.C. ROUTE" at 12393.46,2057.64 h60
  text "X" at 13072.46,2057.64 h60
  text "V. SCORE" at 13259.46,2057.64 h60
  text "CERTIFICATION:" at 11332.46,1920.64 h60
  text "MATERIALS AND WORKMANSHIP FOR ALL PCBS" at 12057.46,1920.64 h60
  text "TO MEET OR EXCEED THE REQUIREMENTS OF:" at 12057.46,1822.64 h60
  text "X" at 11683.96,1686.13 h60
  text "ANSI IPC-A-600F CLASS ->" at 11822.96,1686.13 h60
  text "X" at 13462.02,1686.13 h60
  text "2" at 13580.96,1686.14 h60
  text "1" at 13265.96,1684.64 h60
  text "3" at 13934.96,1684.64 h60
  text "X" at 11686.02,1526.64 h60
  text "UL 94V-0" at 11822.96,1526.64 h60
  text "X" at 12498.02,1526.64 h60
  text "RoHS" at 12634.96,1526.64 h60
  text "OTHER" at 13279.36,1526.64 h60
  text "PER ORDER" at 13676.42,1526.64 h60
  text "ADDITIONAL REQUIREMENTS:" at 11332.46,1385.64 h60
  text "MICROSECTION:" at 11407.23,1270.64 h60
  text "YES" at 12312.96,1270.64 h60
  text "REQUIRED" at 13174.46,1114.49 h60
  text "BARE BOARD ELEC. TEST:" at 11407.23,1111.64 h60
  text "NONE" at 12712.96,1111.64 h60
  text "X" at 13047.46,1111.64 h60
  text "PER ORDER" at 13766.46,1111.64 h60
  text "MANUFACTURER'S UL:" at 11407.23,954.64 h60
  text "RAIL" at 12572.96,950.35 h60
  text "METAL" at 13064.77,950.35 h60
  text "X" at 13440,950 h60
  text "SILK" at 13576.46,950.35 h60
  text ".Layer_Name" at 577,-858.49 h60
M11 Gerber Information:
  lines w10: -292,-930.17 6308,-930.17 ; -292,-726.83 6310,-726.83 ; -292,-523.5 -292,-1133.5 3713,-1133.5 6310,-1133.5 6310,-523.5 -291.5,-523.5 -291.5,-1133.5 1284,-1133.5 ; 2173,-1133.5 2173,-523.5 ; 3440,-726.83 3440,-523.5 ; 4280,-726.83 4280,-523.5 ; 4902,-1140 4902,-937.17
  text "ALL ARTWORK VIEWED FROM TOP SIDE" at -228.5,-655.67 h60
  text "BOARD #:" at 2248,-655.67 h60
  text ".PRJ_Number" at 2793.5,-655.67 h60
  text "REV:" at 3638,-655.67 h60
  text ".PCB_Rev" at 3929.5,-655.67 h60
  text "SVN REV:" at 4476,-655.67 h60
  text ".VersionControl_RevNumber" at 4982,-655.67 h60
  text "LAYER NAME =" at -228.5,-858.49 h60
  text "PLOT NAME =" at -228.5,-1064.34 h60
  text ".plot_File_Name" at 577,-1064.34 h60
  text "GENERATED    :" at 2250,-1064.34 h60
  text ".Print_Date" at 3119.5,-1064.34 h60
  text ".Print_Time" at 3848.5,-1064.34 h60
  text "TEXAS INSTRUMENTS" at 5113,-1064.34 h60
M12 Stackup:
  lines w5: 11370,7697.5 14240,7697.5 ; 11370,7796.8 14240,7796.8 ; 11310,6962 ccw(c11342,6962) 11342,6930 14268,6930 ccw(c14268,6962) 14300,6962 14300,7918 ccw(c14268,7918) 14268,7950 11342,7950 ccw(c11342,7918) 11310,7918 11310,6962
  text "Layer Stack Up Detail for: SAT0060 PCB.PcbDoc" at 11370,7828.7 h59
  text "Layer" at 11370,7759.8 h23
  text "Gerber" at 11986.16,7759.8 h23
  text "Copper" at 12295.75,7759.8 h23
  text "Dielectric" at 12642.89,7759.8 h23
  text "Dielectric" at 13006.13,7759.8 h23
  text "Dielectric" at 13462.34,7759.8 h23
  text "Dielectric" at 13825.58,7759.8 h23
  text "Name" at 11370,7713.8 h23
  text "Document" at 11986.16,7713.8 h23
  text "Thickness" at 12295.75,7713.8 h23
  text "Height" at 12642.89,7713.8 h23
  text "Material" at 13006.13,7713.8 h23
  text "Constant" at 13462.34,7713.8 h23
  text "Type" at 13825.58,7713.8 h23
  text "Top Solder Mask" at 11370,7641.88 h32
  text "(.GTS)" at 11986.16,7641.88 h32
  text "0.4mil" at 12642.89,7641.88 h32
  text "Solder Resist" at 13006.13,7641.88 h32
  text "3.50" at 13462.34,7641.88 h32
  text "Top Layer" at 11370,7535.62 h32
  text "(.GTL)" at 11986.16,7535.62 h32
  text "1.4mil" at 12295.75,7535.62 h32
  text "12.6mil" at 12642.89,7482.5 h32
  text "FR-4 High Tg" at 13006.13,7482.5 h32
  text "4.80" at 13462.34,7482.5 h32
  text "PrePreg" at 13825.58,7482.5 h32
  text "GND" at 11370,7429.38 h32
  text "(.GP1)" at 11986.16,7429.38 h32
  text "1.4mil" at 12295.75,7429.38 h32
  text "30.4mil" at 12642.89,7376.25 h32
  text "FR-4 High Tg" at 13006.13,7376.25 h32
  text "4.80" at 13462.34,7376.25 h32
  text "Core" at 13825.58,7376.25 h32
  text "MidLayer1" at 11370,7323.12 h32
  text "(.G1)" at 11986.16,7323.12 h32
  text "1.4mil" at 12295.75,7323.12 h32
  text "12.6mil" at 12642.89,7270 h32
  text "FR-4 High Tg" at 13006.13,7270 h32
  text "4.80" at 13462.34,7270 h32
  text "PrePreg" at 13825.58,7270 h32
  text "Bottom Layer" at 11370,7216.88 h32
  text "(.GBL)" at 11986.16,7216.88 h32
  text "1.4mil" at 12295.75,7216.88 h32
  text "Bottom Solder Mask" at 11370,7110.62 h32
  text "(.GBS)" at 11986.16,7110.62 h32
  text "0.4mil" at 12642.89,7110.62 h32
  text "Solder Resist" at 13006.13,7110.62 h32
  text "3.50" at 13462.34,7110.62 h32
  text ".Layer_Name" at 577,-858.49 h60
M13 Component Bodies Top:
  text ".Layer_Name" at 577,-858.49 h60
M14 Component Bodies Bottom:
  text ".Layer_Name" at 577,-858.49 h60
M15 Courtyards Top:
  text ".Layer_Name" at 577,-858.49 h60
M16 Courtyards Bottom:
  text ".Layer_Name" at 577,-858.49 h60
Drill Drawing:
  text ".legend" at 5122.5,725.5 h60
  text "Drill Table" at 5147.5,540.5 h60
  text ".Layer_Name" at 577,-858.49 h60

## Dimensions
0,0 to 0,2000 on M2 Board Dimensions
0,0 to 3780,0 on M2 Board Dimensions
